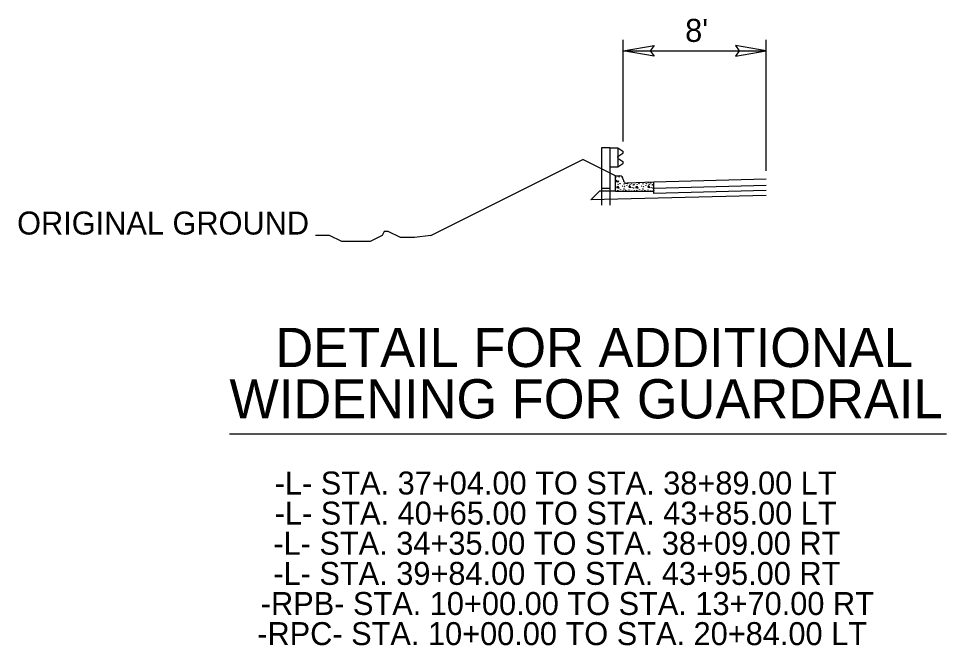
# Model space of a CAD drawing. Extents: x 1640342 to 1730599, y 538663 to 843747.
# Drawn here: x 1730289.1 to 1730345.6, y 540318.9 to 540357.1 of the extents above; entities that cross this region are included whole.
import ezdxf

# ---------------------------------------------------------------- set-up
doc = ezdxf.new("R2010")
doc.units = 0
for name, color, linetype in [('Default', 7, 'Continuous'), ('Prop Dimension Text', 7, 'Continuous'), ('Typical Curb CELL', 7, 'Continuous'), ('Typical Guardrail CELL', 7, 'Continuous'), ('Typical Hinge Slope Arterial CELL', 7, 'Continuous'), ('Typical Pavement Slope CELL', 7, 'Continuous'), ('Typical Text General CELL', 7, 'Continuous'), ('Typical Text Label CELL', 7, 'Continuous')]:
    doc.layers.add(name, color=color, linetype=linetype)

msp = doc.modelspace()

# ---------------------------------------------------------------- linework, layer by layer
at = {"layer": 'Default'}
for p, q in [((1730325.955, 540349.614), (1730325.955, 540355.806)), ((1730334.67, 540347.834), (1730334.67, 540355.806)), ((1730325.955, 540355.136), (1730334.67, 540355.136))]:
    msp.add_line(p, q, dxfattribs=at)
for points in [[(1730327.829, 540354.814), (1730325.955, 540355.136), (1730327.84, 540355.469), (1730327.6, 540355.136)], [(1730332.796, 540354.814), (1730334.67, 540355.136), (1730332.786, 540355.469), (1730333.025, 540355.136)]]:
    msp.add_lwpolyline(points, close=True, dxfattribs=at)
at = {"layer": 'Typical Curb CELL'}
for p, q in [((1730325.491, 540346.599), (1730325.491, 540347.528)), ((1730325.491, 540347.528), (1730325.733, 540347.528)), ((1730325.525, 540347.177), (1730325.668, 540347.219)), ((1730325.652, 540347.134), (1730325.525, 540347.177)), ((1730325.668, 540347.219), (1730325.652, 540347.134)), ((1730325.955, 540347.296), (1730325.955, 540347.306)), ((1730327.813, 540347.141), (1730326.187, 540347.074)), ((1730327.813, 540346.599), (1730327.813, 540347.141)), ((1730325.491, 540346.599), (1730327.813, 540346.599)), ((1730325.642, 540346.881), (1730325.546, 540346.811)), ((1730325.546, 540346.811), (1730325.7, 540346.775)), ((1730325.7, 540346.775), (1730325.642, 540346.881)), ((1730326.331, 540346.933), (1730326.299, 540346.828)), ((1730326.299, 540346.828), (1730326.41, 540346.822)), ((1730326.41, 540346.822), (1730326.331, 540346.933)), ((1730326.802, 540346.881), (1730326.706, 540346.811)), ((1730326.706, 540346.811), (1730326.86, 540346.775)), ((1730326.86, 540346.775), (1730326.802, 540346.881)), ((1730327.491, 540346.933), (1730327.459, 540346.828)), ((1730327.459, 540346.828), (1730327.571, 540346.822)), ((1730327.571, 540346.822), (1730327.491, 540346.933))]:
    msp.add_line(p, q, dxfattribs=at)
for centre in [(1730325.503, 540347.426), (1730325.551, 540347.256), (1730325.705, 540347.458), (1730325.625, 540346.642), (1730325.641, 540347.003), (1730325.753, 540347.05), (1730325.784, 540346.679), (1730325.917, 540346.897), (1730325.949, 540346.621), (1730325.991, 540347.076), (1730326.002, 540346.727), (1730326.007, 540347.029), (1730326.034, 540346.87), (1730326.108, 540346.647), (1730326.171, 540346.95), (1730326.198, 540347.044), (1730326.299, 540346.669), (1730326.378, 540347.008), (1730326.447, 540346.605), (1730326.468, 540347.058), (1730326.495, 540346.822), (1730326.569, 540346.971), (1730326.584, 540346.78), (1730326.621, 540347.003), (1730326.637, 540346.913), (1730326.643, 540346.626), (1730326.786, 540346.642), (1730326.802, 540347.003), (1730326.913, 540347.05), (1730326.945, 540346.679), (1730327.077, 540346.897), (1730327.109, 540346.621), (1730327.152, 540347.076), (1730327.162, 540346.727), (1730327.168, 540347.029), (1730327.194, 540346.87), (1730327.268, 540346.647), (1730327.332, 540346.95), (1730327.358, 540347.044), (1730327.459, 540346.669), (1730327.496, 540347.103), (1730327.539, 540347.008), (1730327.608, 540346.605), (1730327.629, 540347.087), (1730327.655, 540346.822), (1730327.73, 540346.971), (1730327.745, 540346.78), (1730327.782, 540347.003), (1730327.798, 540346.913), (1730327.803, 540346.626)]:
    msp.add_circle(centre, 0.00745, dxfattribs=at)
for centre, start, end in [((1730325.733, 540347.306), 0, 90), ((1730326.178, 540347.296), 180, 272.3845)]:
    msp.add_arc(centre, 0.223, start, end, dxfattribs=at)
at = {"layer": 'Typical Guardrail CELL'}
for p, q in [((1730325.135, 540349.23), (1730324.638, 540349.23)), ((1730324.638, 540349.23), (1730324.638, 540346.745)), ((1730325.135, 540349.23), (1730325.135, 540346.745)), ((1730325.135, 540349.23), (1730325.632, 540349.23)), ((1730325.632, 540349.23), (1730325.632, 540348.07)), ((1730325.632, 540349.23), (1730325.922, 540349.027)), ((1730325.632, 540348.697), (1730325.922, 540348.9)), ((1730325.632, 540348.65), (1730325.632, 540348.697)), ((1730325.632, 540348.65), (1730325.632, 540348.604)), ((1730325.632, 540348.604), (1730325.922, 540348.401)), ((1730325.632, 540348.07), (1730325.922, 540348.273)), ((1730325.135, 540348.07), (1730325.632, 540348.07)), ((1730325.135, 540346.745), (1730324.638, 540346.745)), ((1730324.638, 540346.745), (1730324.638, 540345.736)), ((1730325.135, 540346.745), (1730325.135, 540345.736))]:
    msp.add_line(p, q, dxfattribs=at)
for centre, start, end in [((1730325.878, 540348.964), 304.9888, 54.997), ((1730325.878, 540348.337), 304.9634, 54.9941)]:
    msp.add_arc(centre, 0.0776, start, end, dxfattribs=at)
at = {"layer": 'Typical Hinge Slope Arterial CELL'}
msp.add_lwpolyline([(1730314.224, 540343.895), (1730313.239, 540343.772), (1730312.992, 540343.772), (1730312.622, 540343.772), (1730312.376, 540343.772), (1730312.13, 540343.895), (1730311.883, 540344.019), (1730311.637, 540344.142), (1730311.391, 540344.142), (1730311.267, 540343.895), (1730311.02, 540343.772), (1730310.774, 540343.649), (1730310.528, 540343.526), (1730310.281, 540343.526), (1730310.035, 540343.526), (1730309.789, 540343.526), (1730309.542, 540343.526), (1730309.296, 540343.526), (1730309.05, 540343.526), (1730308.803, 540343.526), (1730308.557, 540343.649), (1730308.31, 540343.772), (1730308.064, 540343.895), (1730307.694, 540343.895), (1730307.448, 540343.895), (1730307.201, 540343.895)], dxfattribs=at)
at = {"layer": 'Typical Pavement Slope CELL'}
for p, q in [((1730314.224, 540343.895), (1730323.491, 540348.528)), ((1730325.491, 540347.528), (1730323.491, 540348.528)), ((1730334.67, 540347.313), (1730327.813, 540347.141)), ((1730324.515, 540346.599), (1730323.978, 540346.062)), ((1730325.491, 540346.599), (1730324.515, 540346.599)), ((1730334.67, 540346.629), (1730327.803, 540346.457)), ((1730334.67, 540346.929), (1730327.808, 540346.758)), ((1730327.813, 540346.458), (1730327.813, 540346.599)), ((1730334.67, 540346.329), (1730323.978, 540346.062))]:
    msp.add_line(p, q, dxfattribs=at)
at = {"layer": 'Typical Text Label CELL'}
msp.add_line((1730301.96, 540331.808), (1730345.644, 540331.808), dxfattribs=at)

# ---------------------------------------------------------------- texts
at = {"layer": 'Prop Dimension Text'}
msp.add_text("8'", height=1.4, rotation=360, dxfattribs=at).set_placement((1730329.725, 540355.686))
at = {"layer": 'Typical Hinge Slope Arterial CELL'}
msp.add_text('ORIGINAL GROUND', height=1.4, dxfattribs=at).set_placement((1730289.025, 540343.947))
at = {"layer": 'Typical Text General CELL'}
for s, p in [('DETAIL FOR ADDITIONAL', (1730304.758, 540335.875)), ('WIDENING FOR GUARDRAIL', (1730301.96, 540332.746))]:
    msp.add_text(s, height=2.38712, dxfattribs=at).set_placement(p)
at = {"layer": 'Typical Text Label CELL'}
for s, p in [('-L- STA. 37+04.00 TO STA. 38+89.00 LT', (1730304.717, 540328.108)), ('-L- STA. 40+65.00 TO STA. 43+85.00 LT', (1730304.717, 540326.273)), ('-L- STA. 34+35.00 TO STA. 38+09.00 RT', (1730304.634, 540324.438)), ('-L- STA. 39+84.00 TO STA. 43+95.00 RT', (1730304.634, 540322.602)), ('-RPB- STA. 10+00.00 TO STA. 13+70.00 RT', (1730303.871, 540320.767)), ('-RPC- STA. 10+00.00 TO STA. 20+84.00 LT', (1730303.656, 540318.932))]:
    msp.add_text(s, height=1.4, dxfattribs=at).set_placement(p)

doc.saveas('drawing.dxf')
